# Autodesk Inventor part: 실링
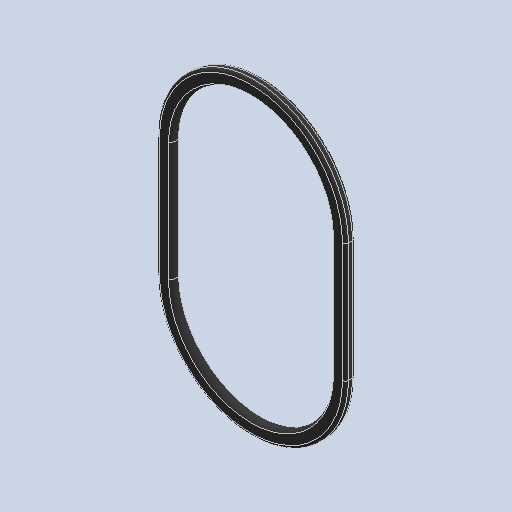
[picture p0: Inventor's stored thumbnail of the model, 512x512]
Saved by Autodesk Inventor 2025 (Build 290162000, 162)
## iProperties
Created: 2026-08
Part Number: 실링
Material: 고무
Document SubType Name: Modeling
Designer: KDI
Density: 0.93 g/cm^3
Appearance: 기본값
Author: jhkim
Sending System: Autodesk Inventor 2027
Preprocessor: ST-DEVELOPER v20.1
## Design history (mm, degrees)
feature "솔리드3"
node "솔리드1"
